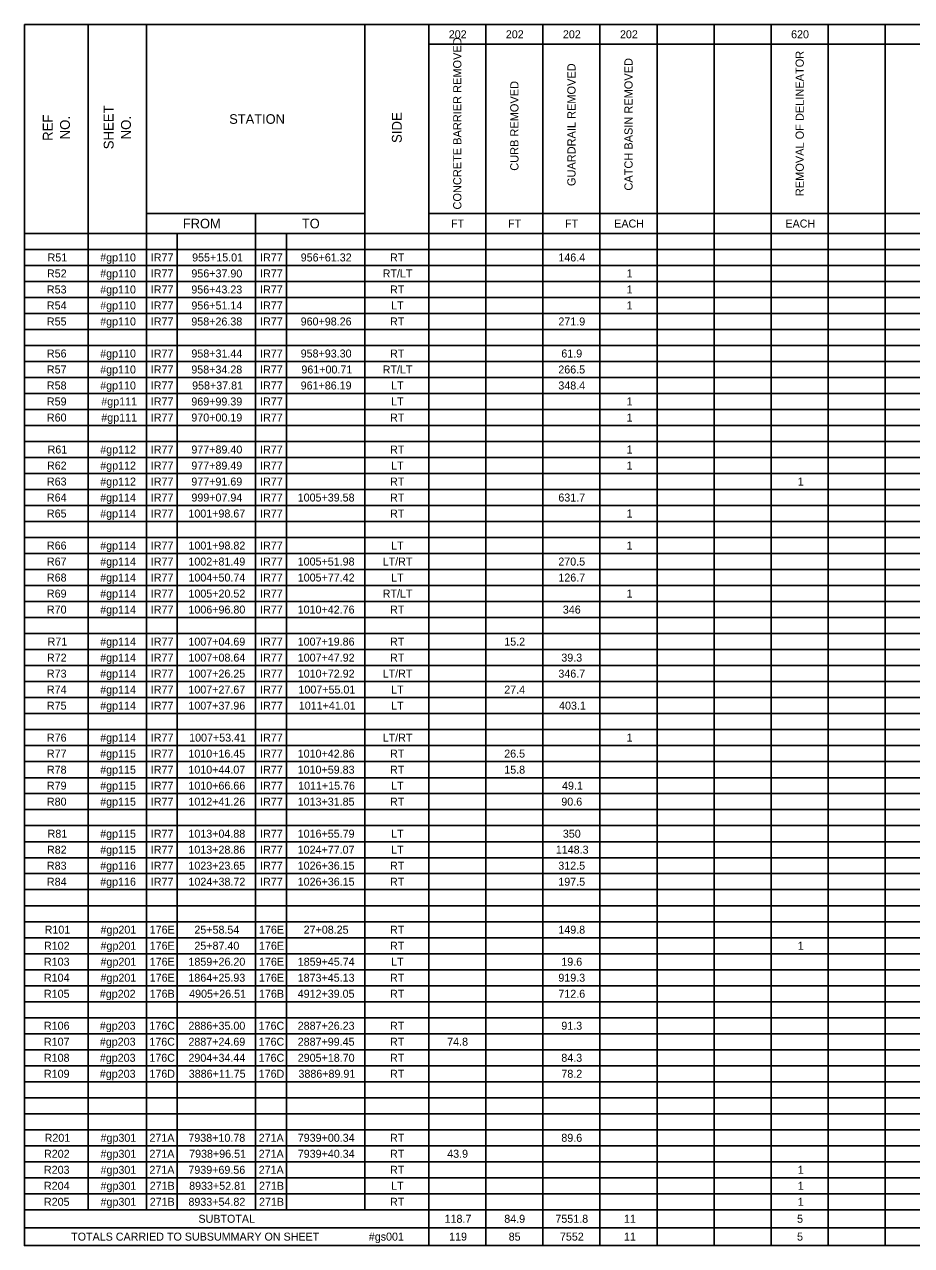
# Model space of a CAD drawing. Extents: x -542 to 295, y -281 to 32.
# Drawn here: x -16.36 to -1.11, y -40.59 to -19.59 of the extents above; entities that cross this region are included whole.
import ezdxf

# ---------------------------------------------------------------- set-up
doc = ezdxf.new("R2010")
doc.units = 0
doc.layers.add('SC_Scratch1', color=7, linetype='Continuous')
doc.layers.add('SH_Text', color=7, linetype='Continuous')

msp = doc.modelspace()

# ---------------------------------------------------------------- linework, layer by layer
at = {"layer": 'SC_Scratch1'}
msp.add_lwpolyline([(-16.359, -19.593), (14.141, -19.593), (14.141, -40.593), (-16.359, -40.593)], close=True, dxfattribs=at)
at = {"layer": 'SH_Text'}
for p, q in [((-16.359, -19.593), (14.136, -19.593)), ((-16.359, -19.593), (-16.359, -40.594)), ((-15.261, -19.593), (-15.261, -39.979)), ((-14.263, -19.593), (-14.263, -39.979)), ((-10.506, -19.593), (-10.506, -39.979)), ((-9.408, -19.593), (-9.408, -40.594)), ((-8.427, -19.593), (-8.427, -40.594)), ((-7.446, -19.593), (-7.446, -40.594)), ((-6.465, -19.593), (-6.465, -40.594)), ((-5.484, -19.593), (-5.484, -40.594)), ((-4.503, -19.593), (-4.503, -40.594)), ((-3.522, -19.593), (-3.522, -40.594)), ((-2.541, -19.593), (-2.541, -40.594)), ((-1.56, -19.593), (-1.56, -40.594)), ((-9.408, -19.933), (14.136, -19.933)), ((-14.263, -22.847), (-10.506, -22.847)), ((-12.385, -22.847), (-12.385, -39.979)), ((-9.408, -22.847), (14.136, -22.847)), ((-16.359, -23.187), (14.136, -23.187)), ((-13.731, -23.187), (-13.731, -39.979)), ((-11.852, -23.187), (-11.852, -39.979)), ((-16.359, -23.463), (14.136, -23.463)), ((-16.359, -23.738), (14.136, -23.738)), ((-16.359, -24.013), (14.136, -24.013)), ((-16.359, -24.288), (14.136, -24.288)), ((-16.359, -24.564), (14.136, -24.564)), ((-16.359, -24.839), (14.136, -24.839)), ((-16.359, -25.114), (14.136, -25.114)), ((-16.359, -25.389), (14.136, -25.389)), ((-16.359, -25.665), (14.136, -25.665)), ((-16.359, -25.94), (14.136, -25.94)), ((-16.359, -26.215), (14.136, -26.215)), ((-16.359, -26.491), (14.136, -26.491)), ((-16.359, -26.766), (14.136, -26.766)), ((-16.359, -27.041), (14.136, -27.041)), ((-16.359, -27.316), (14.136, -27.316)), ((-16.359, -27.592), (14.136, -27.592)), ((-16.359, -27.867), (14.136, -27.867)), ((-16.359, -28.142), (14.136, -28.142)), ((-16.359, -28.417), (14.136, -28.417)), ((-16.359, -28.693), (14.136, -28.693)), ((-16.359, -28.968), (14.136, -28.968)), ((-16.359, -29.243), (14.136, -29.243)), ((-16.359, -29.519), (14.136, -29.519)), ((-16.359, -29.794), (14.136, -29.794)), ((-16.359, -30.069), (14.136, -30.069)), ((-16.359, -30.344), (14.136, -30.344)), ((-16.359, -30.62), (14.136, -30.62)), ((-16.359, -30.895), (14.136, -30.895)), ((-16.359, -31.17), (14.136, -31.17)), ((-16.359, -31.445), (14.136, -31.445)), ((-16.359, -31.721), (14.136, -31.721)), ((-16.359, -31.996), (14.136, -31.996)), ((-16.359, -32.271), (14.136, -32.271)), ((-16.359, -32.547), (14.136, -32.547)), ((-16.359, -32.822), (14.136, -32.822)), ((-16.359, -33.097), (14.136, -33.097)), ((-16.359, -33.372), (14.136, -33.372)), ((-16.359, -33.648), (14.136, -33.648)), ((-16.359, -33.923), (14.136, -33.923)), ((-16.359, -34.198), (14.136, -34.198)), ((-16.359, -34.473), (14.136, -34.473)), ((-16.359, -34.749), (14.136, -34.749)), ((-16.359, -35.024), (14.136, -35.024)), ((-16.359, -35.299), (14.136, -35.299)), ((-16.359, -35.575), (14.136, -35.575)), ((-16.359, -35.85), (14.136, -35.85)), ((-16.359, -36.125), (14.136, -36.125)), ((-16.359, -36.4), (14.136, -36.4)), ((-16.359, -36.676), (14.136, -36.676)), ((-16.359, -36.951), (14.136, -36.951)), ((-16.359, -37.226), (14.136, -37.226)), ((-16.359, -37.501), (14.136, -37.501)), ((-16.359, -37.777), (14.136, -37.777)), ((-16.359, -38.052), (14.136, -38.052)), ((-16.359, -38.327), (14.136, -38.327)), ((-16.359, -38.603), (14.136, -38.603)), ((-16.359, -38.878), (14.136, -38.878)), ((-16.359, -39.153), (14.136, -39.153)), ((-16.359, -39.428), (14.136, -39.428)), ((-16.359, -39.704), (14.136, -39.704)), ((-16.359, -39.979), (14.136, -39.979)), ((-16.359, -40.287), (14.136, -40.287)), ((-16.359, -40.594), (14.136, -40.594))]:
    msp.add_line(p, q, dxfattribs=at)

# ---------------------------------------------------------------- texts
for s, height, p in [('202', 0.1376, (-9.064, -19.831)), ('202', 0.1376, (-8.083, -19.831)), ('202', 0.1376, (-7.102, -19.831)), ('202', 0.1376, (-6.121, -19.831)), ('620', 0.1376, (-3.179, -19.831)), ('STATION', 0.1652, (-12.838, -21.302)), ('FROM', 0.1652, (-13.635, -23.1)), ('TO', 0.1652, (-11.589, -23.1)), ('FT', 0.1376, (-9.026, -23.086)), ('FT', 0.1376, (-8.045, -23.086)), ('FT', 0.1376, (-7.064, -23.086)), ('EACH', 0.1376, (-6.219, -23.086)), ('EACH', 0.1376, (-3.276, -23.086)), ('R51', 0.1376, (-15.96, -23.669)), ('#gp110', 0.1376, (-15.056, -23.669)), ('IR77', 0.1376, (-14.186, -23.669)), ('955+15.01', 0.1376, (-13.476, -23.669)), ('IR77', 0.1376, (-12.307, -23.669)), ('956+61.32', 0.1376, (-11.609, -23.669)), ('RT', 0.1376, (-10.074, -23.669)), ('146.4', 0.1376, (-7.18, -23.669)), ('R52', 0.1376, (-15.971, -23.944)), ('#gp110', 0.1376, (-15.056, -23.944)), ('IR77', 0.1376, (-14.186, -23.944)), ('956+37.90', 0.1376, (-13.488, -23.944)), ('IR77', 0.1376, (-12.307, -23.944)), ('RT/LT', 0.1376, (-10.2, -23.944)), ('1', 0.138, (-6.008, -23.944)), ('R53', 0.1376, (-15.972, -24.22)), ('#gp110', 0.1376, (-15.056, -24.22)), ('IR77', 0.1376, (-14.186, -24.22)), ('956+43.23', 0.1376, (-13.489, -24.22)), ('IR77', 0.1376, (-12.307, -24.22)), ('RT', 0.1376, (-10.074, -24.22)), ('1', 0.138, (-6.008, -24.22)), ('R54', 0.1376, (-15.972, -24.495)), ('#gp110', 0.1376, (-15.056, -24.495)), ('IR77', 0.1376, (-14.186, -24.495)), ('956+51.14', 0.1376, (-13.488, -24.495)), ('IR77', 0.1376, (-12.307, -24.495)), ('LT', 0.1376, (-10.054, -24.495)), ('1', 0.138, (-6.008, -24.495)), ('R55', 0.1376, (-15.972, -24.77)), ('#gp110', 0.1376, (-15.056, -24.77)), ('IR77', 0.1376, (-14.186, -24.77)), ('958+26.38', 0.1376, (-13.489, -24.77)), ('IR77', 0.1376, (-12.307, -24.77)), ('960+98.26', 0.1376, (-11.61, -24.77)), ('RT', 0.1376, (-10.074, -24.77)), ('271.9', 0.1376, (-7.18, -24.77)), ('R56', 0.1376, (-15.972, -25.321)), ('#gp110', 0.1376, (-15.056, -25.321)), ('IR77', 0.1376, (-14.186, -25.321)), ('958+31.44', 0.1376, (-13.488, -25.321)), ('IR77', 0.1376, (-12.307, -25.321)), ('958+93.30', 0.1376, (-11.61, -25.321)), ('RT', 0.1376, (-10.074, -25.321)), ('61.9', 0.1376, (-7.129, -25.321)), ('R57', 0.1376, (-15.972, -25.596)), ('#gp110', 0.1376, (-15.056, -25.596)), ('IR77', 0.1376, (-14.186, -25.596)), ('958+34.28', 0.1376, (-13.489, -25.596)), ('IR77', 0.1376, (-12.307, -25.596)), ('961+00.71', 0.1376, (-11.597, -25.596)), ('RT/LT', 0.1376, (-10.2, -25.596)), ('266.5', 0.1376, (-7.181, -25.596)), ('R58', 0.1376, (-15.972, -25.871)), ('#gp110', 0.1376, (-15.056, -25.871)), ('IR77', 0.1376, (-14.186, -25.871)), ('958+37.81', 0.1376, (-13.476, -25.871)), ('IR77', 0.1376, (-12.307, -25.871)), ('961+86.19', 0.1376, (-11.61, -25.871)), ('LT', 0.1376, (-10.054, -25.871)), ('348.4', 0.1376, (-7.18, -25.871)), ('R59', 0.1376, (-15.972, -26.146)), ('#gp111', 0.1376, (-15.037, -26.146)), ('IR77', 0.1376, (-14.186, -26.146)), ('969+99.39', 0.1376, (-13.489, -26.146)), ('IR77', 0.1376, (-12.307, -26.146)), ('LT', 0.1376, (-10.054, -26.146)), ('1', 0.138, (-6.008, -26.146)), ('R60', 0.1376, (-15.972, -26.422)), ('#gp111', 0.1376, (-15.037, -26.422)), ('IR77', 0.1376, (-14.186, -26.422)), ('970+00.19', 0.1376, (-13.489, -26.422)), ('IR77', 0.1376, (-12.307, -26.422)), ('RT', 0.1376, (-10.074, -26.422)), ('1', 0.138, (-6.008, -26.422)), ('R61', 0.1376, (-15.96, -26.972)), ('#gp112', 0.1376, (-15.055, -26.972)), ('IR77', 0.1376, (-14.186, -26.972)), ('977+89.40', 0.1376, (-13.488, -26.972)), ('IR77', 0.1376, (-12.307, -26.972)), ('RT', 0.1376, (-10.074, -26.972)), ('1', 0.138, (-6.008, -26.972)), ('R62', 0.1376, (-15.971, -27.248)), ('#gp112', 0.1376, (-15.055, -27.248)), ('IR77', 0.1376, (-14.186, -27.248)), ('977+89.49', 0.1376, (-13.489, -27.248)), ('IR77', 0.1376, (-12.307, -27.248)), ('LT', 0.1376, (-10.054, -27.248)), ('1', 0.138, (-6.008, -27.248)), ('R63', 0.1376, (-15.972, -27.523)), ('#gp112', 0.1376, (-15.055, -27.523)), ('IR77', 0.1376, (-14.186, -27.523)), ('977+91.69', 0.1376, (-13.489, -27.523)), ('IR77', 0.1376, (-12.307, -27.523)), ('RT', 0.1376, (-10.074, -27.523)), ('1', 0.138, (-3.065, -27.523)), ('R64', 0.1376, (-15.972, -27.798)), ('#gp114', 0.1376, (-15.056, -27.798)), ('IR77', 0.1376, (-14.186, -27.798)), ('999+07.94', 0.1376, (-13.488, -27.798)), ('IR77', 0.1376, (-12.307, -27.798)), ('1005+39.58', 0.1376, (-11.661, -27.798)), ('RT', 0.1376, (-10.074, -27.798)), ('631.7', 0.1376, (-7.18, -27.798)), ('R65', 0.1376, (-15.972, -28.073)), ('#gp114', 0.1376, (-15.056, -28.073)), ('IR77', 0.1376, (-14.186, -28.073)), ('1001+98.67', 0.1376, (-13.54, -28.073)), ('IR77', 0.1376, (-12.307, -28.073)), ('RT', 0.1376, (-10.074, -28.073)), ('1', 0.138, (-6.008, -28.073)), ('R66', 0.1376, (-15.972, -28.624)), ('#gp114', 0.1376, (-15.056, -28.624)), ('IR77', 0.1376, (-14.186, -28.624)), ('1001+98.82', 0.1376, (-13.539, -28.624)), ('IR77', 0.1376, (-12.307, -28.624)), ('LT', 0.1376, (-10.054, -28.624)), ('1', 0.138, (-6.008, -28.624)), ('R67', 0.1376, (-15.972, -28.899)), ('#gp114', 0.1376, (-15.056, -28.899)), ('IR77', 0.1376, (-14.186, -28.899)), ('1002+81.49', 0.1376, (-13.54, -28.899)), ('IR77', 0.1376, (-12.307, -28.899)), ('1005+51.98', 0.1376, (-11.661, -28.899)), ('LT/RT', 0.1376, (-10.2, -28.899)), ('270.5', 0.1376, (-7.181, -28.899)), ('R68', 0.1376, (-15.972, -29.174)), ('#gp114', 0.1376, (-15.056, -29.174)), ('IR77', 0.1376, (-14.186, -29.174)), ('1004+50.74', 0.1376, (-13.539, -29.174)), ('IR77', 0.1376, (-12.307, -29.174)), ('1005+77.42', 0.1376, (-11.66, -29.174)), ('LT', 0.1376, (-10.054, -29.174)), ('126.7', 0.1376, (-7.18, -29.174)), ('R69', 0.1376, (-15.972, -29.45)), ('#gp114', 0.1376, (-15.056, -29.45)), ('IR77', 0.1376, (-14.186, -29.45)), ('1005+20.52', 0.1376, (-13.539, -29.45)), ('IR77', 0.1376, (-12.307, -29.45)), ('RT/LT', 0.1376, (-10.2, -29.45)), ('1', 0.138, (-6.008, -29.45)), ('R70', 0.1376, (-15.972, -29.725)), ('#gp114', 0.1376, (-15.056, -29.725)), ('IR77', 0.1376, (-14.186, -29.725)), ('1006+96.80', 0.1376, (-13.539, -29.725)), ('IR77', 0.1376, (-12.307, -29.725)), ('1010+42.76', 0.1376, (-11.661, -29.725)), ('RT', 0.1376, (-10.074, -29.725)), ('346', 0.1376, (-7.103, -29.725)), ('R71', 0.1376, (-15.96, -30.276)), ('#gp114', 0.1376, (-15.056, -30.276)), ('IR77', 0.1376, (-14.186, -30.276)), ('1007+04.69', 0.1376, (-13.54, -30.276)), ('IR77', 0.1376, (-12.307, -30.276)), ('1007+19.86', 0.1376, (-11.661, -30.276)), ('RT', 0.1376, (-10.074, -30.276)), ('15.2', 0.1376, (-8.11, -30.276)), ('R72', 0.1376, (-15.971, -30.551)), ('#gp114', 0.1376, (-15.056, -30.551)), ('IR77', 0.1376, (-14.186, -30.551)), ('1007+08.64', 0.1376, (-13.539, -30.551)), ('IR77', 0.1376, (-12.307, -30.551)), ('1007+47.92', 0.1376, (-11.66, -30.551)), ('RT', 0.1376, (-10.074, -30.551)), ('39.3', 0.1376, (-7.129, -30.551)), ('R73', 0.1376, (-15.972, -30.826)), ('#gp114', 0.1376, (-15.056, -30.826)), ('IR77', 0.1376, (-14.186, -30.826)), ('1007+26.25', 0.1376, (-13.54, -30.826)), ('IR77', 0.1376, (-12.307, -30.826)), ('1010+72.92', 0.1376, (-11.66, -30.826)), ('LT/RT', 0.1376, (-10.2, -30.826)), ('346.7', 0.1376, (-7.18, -30.826)), ('R74', 0.1376, (-15.972, -31.101)), ('#gp114', 0.1376, (-15.056, -31.101)), ('IR77', 0.1376, (-14.186, -31.101)), ('1007+27.67', 0.1376, (-13.54, -31.101)), ('IR77', 0.1376, (-12.307, -31.101)), ('1007+55.01', 0.1376, (-11.648, -31.101)), ('LT', 0.1376, (-10.054, -31.101)), ('27.4', 0.1376, (-8.11, -31.101)), ('R75', 0.1376, (-15.972, -31.377)), ('#gp114', 0.1376, (-15.056, -31.377)), ('IR77', 0.1376, (-14.186, -31.377)), ('1007+37.96', 0.1376, (-13.54, -31.377)), ('IR77', 0.1376, (-12.307, -31.377)), ('1011+41.01', 0.1376, (-11.642, -31.377)), ('LT', 0.1376, (-10.054, -31.377)), ('403.1', 0.1376, (-7.168, -31.377)), ('R76', 0.1376, (-15.972, -31.927)), ('#gp114', 0.1376, (-15.056, -31.927)), ('IR77', 0.1376, (-14.186, -31.927)), ('1007+53.41', 0.1376, (-13.527, -31.927)), ('IR77', 0.1376, (-12.307, -31.927)), ('LT/RT', 0.1376, (-10.2, -31.927)), ('1', 0.138, (-6.008, -31.927)), ('R77', 0.1376, (-15.972, -32.202)), ('#gp115', 0.1376, (-15.056, -32.202)), ('IR77', 0.1376, (-14.186, -32.202)), ('1010+16.45', 0.1376, (-13.54, -32.202)), ('IR77', 0.1376, (-12.307, -32.202)), ('1010+42.86', 0.1376, (-11.661, -32.202)), ('RT', 0.1376, (-10.074, -32.202)), ('26.5', 0.1376, (-8.111, -32.202)), ('R78', 0.1376, (-15.972, -32.478)), ('#gp115', 0.1376, (-15.056, -32.478)), ('IR77', 0.1376, (-14.186, -32.478)), ('1010+44.07', 0.1376, (-13.54, -32.478)), ('IR77', 0.1376, (-12.307, -32.478)), ('1010+59.83', 0.1376, (-11.661, -32.478)), ('RT', 0.1376, (-10.074, -32.478)), ('15.8', 0.1376, (-8.11, -32.478)), ('R79', 0.1376, (-15.972, -32.753)), ('#gp115', 0.1376, (-15.056, -32.753)), ('IR77', 0.1376, (-14.186, -32.753)), ('1010+66.66', 0.1376, (-13.54, -32.753)), ('IR77', 0.1376, (-12.307, -32.753)), ('1011+15.76', 0.1376, (-11.654, -32.753)), ('LT', 0.1376, (-10.054, -32.753)), ('49.1', 0.1376, (-7.117, -32.753)), ('R80', 0.1376, (-15.972, -33.028)), ('#gp115', 0.1376, (-15.056, -33.028)), ('IR77', 0.1376, (-14.186, -33.028)), ('1012+41.26', 0.1376, (-13.54, -33.028)), ('IR77', 0.1376, (-12.307, -33.028)), ('1013+31.85', 0.1376, (-11.661, -33.028)), ('RT', 0.1376, (-10.074, -33.028)), ('90.6', 0.1376, (-7.129, -33.028)), ('R81', 0.1376, (-15.96, -33.579)), ('#gp115', 0.1376, (-15.056, -33.579)), ('IR77', 0.1376, (-14.186, -33.579)), ('1013+04.88', 0.1376, (-13.54, -33.579)), ('IR77', 0.1376, (-12.307, -33.579)), ('1016+55.79', 0.1376, (-11.661, -33.579)), ('LT', 0.1376, (-10.054, -33.579)), ('350', 0.1376, (-7.103, -33.579)), ('R82', 0.1376, (-15.971, -33.854)), ('#gp115', 0.1376, (-15.056, -33.854)), ('IR77', 0.1376, (-14.186, -33.854)), ('1013+28.86', 0.1376, (-13.54, -33.854)), ('IR77', 0.1376, (-12.307, -33.854)), ('1024+77.07', 0.1376, (-11.661, -33.854)), ('LT', 0.1376, (-10.054, -33.854)), ('1148.3', 0.1376, (-7.224, -33.854)), ('R83', 0.1376, (-15.972, -34.129)), ('#gp116', 0.1376, (-15.056, -34.129)), ('IR77', 0.1376, (-14.186, -34.129)), ('1023+23.65', 0.1376, (-13.54, -34.129)), ('IR77', 0.1376, (-12.307, -34.129)), ('1026+36.15', 0.1376, (-11.661, -34.129)), ('RT', 0.1376, (-10.074, -34.129)), ('312.5', 0.1376, (-7.181, -34.129)), ('R84', 0.1376, (-15.972, -34.405)), ('#gp116', 0.1376, (-15.056, -34.405)), ('IR77', 0.1376, (-14.186, -34.405)), ('1024+38.72', 0.1376, (-13.539, -34.405)), ('IR77', 0.1376, (-12.307, -34.405)), ('1026+36.15', 0.1376, (-11.661, -34.405)), ('RT', 0.1376, (-10.074, -34.405)), ('197.5', 0.1376, (-7.181, -34.405)), ('R101', 0.1376, (-16.011, -35.23)), ('#gp201', 0.1376, (-15.05, -35.23)), ('176E', 0.1376, (-14.205, -35.23)), ('25+58.54', 0.1376, (-13.437, -35.23)), ('176E', 0.1376, (-12.326, -35.23)), ('27+08.25', 0.1376, (-11.559, -35.23)), ('RT', 0.1376, (-10.074, -35.23)), ('149.8', 0.1376, (-7.18, -35.23)), ('R102', 0.1376, (-16.022, -35.506)), ('#gp201', 0.1376, (-15.05, -35.506)), ('176E', 0.1376, (-14.205, -35.506)), ('25+87.40', 0.1376, (-13.437, -35.506)), ('176E', 0.1376, (-12.326, -35.506)), ('RT', 0.1376, (-10.074, -35.506)), ('1', 0.138, (-3.065, -35.506)), ('R103', 0.1376, (-16.023, -35.781)), ('#gp201', 0.1376, (-15.05, -35.781)), ('176E', 0.1376, (-14.205, -35.781)), ('1859+26.20', 0.1376, (-13.539, -35.781)), ('176E', 0.1376, (-12.326, -35.781)), ('1859+45.74', 0.1376, (-11.66, -35.781)), ('LT', 0.1376, (-10.054, -35.781)), ('19.6', 0.1376, (-7.129, -35.781)), ('R104', 0.1376, (-16.023, -36.056)), ('#gp201', 0.1376, (-15.05, -36.056)), ('176E', 0.1376, (-14.205, -36.056)), ('1864+25.93', 0.1376, (-13.54, -36.056)), ('176E', 0.1376, (-12.326, -36.056)), ('1873+45.13', 0.1376, (-11.661, -36.056)), ('RT', 0.1376, (-10.074, -36.056)), ('919.3', 0.1376, (-7.18, -36.056)), ('R105', 0.1376, (-16.023, -36.332)), ('#gp202', 0.1376, (-15.062, -36.332)), ('176B', 0.1376, (-14.205, -36.332)), ('4905+26.51', 0.1376, (-13.527, -36.332)), ('176B', 0.1376, (-12.326, -36.332)), ('4912+39.05', 0.1376, (-11.661, -36.332)), ('RT', 0.1376, (-10.074, -36.332)), ('712.6', 0.1376, (-7.18, -36.332)), ('R106', 0.1376, (-16.023, -36.882)), ('#gp203', 0.1376, (-15.062, -36.882)), ('176C', 0.1376, (-14.211, -36.882)), ('2886+35.00', 0.1376, (-13.539, -36.882)), ('176C', 0.1376, (-12.332, -36.882)), ('2887+26.23', 0.1376, (-11.661, -36.882)), ('RT', 0.1376, (-10.074, -36.882)), ('91.3', 0.1376, (-7.129, -36.882)), ('R107', 0.1376, (-16.023, -37.157)), ('#gp203', 0.1376, (-15.062, -37.157)), ('176C', 0.1376, (-14.211, -37.157)), ('2887+24.69', 0.1376, (-13.54, -37.157)), ('176C', 0.1376, (-12.332, -37.157)), ('2887+99.45', 0.1376, (-11.661, -37.157)), ('RT', 0.1376, (-10.074, -37.157)), ('74.8', 0.1376, (-9.091, -37.157)), ('R108', 0.1376, (-16.023, -37.433)), ('#gp203', 0.1376, (-15.062, -37.433)), ('176C', 0.1376, (-14.211, -37.433)), ('2904+34.44', 0.1376, (-13.539, -37.433)), ('176C', 0.1376, (-12.332, -37.433)), ('2905+18.70', 0.1376, (-11.66, -37.433)), ('RT', 0.1376, (-10.074, -37.433)), ('84.3', 0.1376, (-7.129, -37.433)), ('R109', 0.1376, (-16.023, -37.708)), ('#gp203', 0.1376, (-15.062, -37.708)), ('176D', 0.1376, (-14.21, -37.708)), ('3886+11.75', 0.1376, (-13.534, -37.708)), ('176D', 0.1376, (-12.331, -37.708)), ('3886+89.91', 0.1376, (-11.648, -37.708)), ('RT', 0.1376, (-10.074, -37.708)), ('78.2', 0.1376, (-7.128, -37.708)), ('R201', 0.1376, (-16.011, -38.809)), ('#gp301', 0.1376, (-15.05, -38.809)), ('271A', 0.1376, (-14.21, -38.809)), ('7938+10.78', 0.1376, (-13.54, -38.809)), ('271A', 0.1376, (-12.331, -38.809)), ('7939+00.34', 0.1376, (-11.66, -38.809)), ('RT', 0.1376, (-10.074, -38.809)), ('89.6', 0.1376, (-7.129, -38.809)), ('R202', 0.1376, (-16.022, -39.084)), ('#gp301', 0.1376, (-15.05, -39.084)), ('271A', 0.1376, (-14.21, -39.084)), ('7938+96.51', 0.1376, (-13.527, -39.084)), ('271A', 0.1376, (-12.331, -39.084)), ('7939+40.34', 0.1376, (-11.66, -39.084)), ('RT', 0.1376, (-10.074, -39.084)), ('43.9', 0.1376, (-9.091, -39.084)), ('R203', 0.1376, (-16.023, -39.36)), ('#gp301', 0.1376, (-15.05, -39.36)), ('271A', 0.1376, (-14.21, -39.36)), ('7939+69.56', 0.1376, (-13.54, -39.36)), ('271A', 0.1376, (-12.331, -39.36)), ('RT', 0.1376, (-10.074, -39.36)), ('1', 0.138, (-3.065, -39.36)), ('R204', 0.1376, (-16.023, -39.635)), ('#gp301', 0.1376, (-15.05, -39.635)), ('271B', 0.1376, (-14.205, -39.635)), ('8933+52.81', 0.1376, (-13.527, -39.635)), ('271B', 0.1376, (-12.326, -39.635)), ('LT', 0.1376, (-10.054, -39.635)), ('1', 0.138, (-3.065, -39.635)), ('R205', 0.1376, (-16.023, -39.91)), ('#gp301', 0.1376, (-15.05, -39.91)), ('271B', 0.1376, (-14.205, -39.91)), ('8933+54.82', 0.1376, (-13.539, -39.91)), ('271B', 0.1376, (-12.326, -39.91)), ('RT', 0.1376, (-10.074, -39.91)), ('1', 0.138, (-3.065, -39.91)), ('SUBTOTAL', 0.1376, (-13.367, -40.202)), ('118.7', 0.1376, (-9.136, -40.202)), ('84.9', 0.1376, (-8.11, -40.202)), ('7551.8', 0.1376, (-7.231, -40.202)), ('11', 0.1376, (-6.052, -40.202)), ('5', 0.138, (-3.077, -40.202)), ('TOTALS CARRIED TO SUBSUMMARY ON SHEET', 0.13764, (-15.555, -40.509)), ('#gs001', 0.1376, (-10.439, -40.509)), ('119', 0.1376, (-9.058, -40.509)), ('85', 0.1376, (-8.034, -40.509)), ('7552', 0.1376, (-7.153, -40.509)), ('11', 0.1376, (-6.052, -40.509)), ('5', 0.138, (-3.077, -40.509))]:
    msp.add_text(s, height=height, dxfattribs=at).set_placement(p)
for s, height, p in [('CONCRETE BARRIER REMOVED', 0.14133, (-8.847, -22.776)), ('REMOVAL OF DELINEATOR', 0.14133, (-2.961, -22.546)), ('GUARDRAIL REMOVED', 0.14133, (-6.885, -22.373)), ('CATCH BASIN REMOVED', 0.14133, (-5.904, -22.45)), ('CURB REMOVED', 0.14133, (-7.866, -22.109)), ('SHEET', 0.1696, (-14.826, -21.74)), ('REF', 0.1696, (-15.873, -21.596)), ('NO.', 0.1696, (-15.577, -21.57)), ('NO.', 0.1696, (-14.529, -21.57)), ('SIDE', 0.1696, (-9.872, -21.632))]:
    msp.add_text(s, height=height, rotation=90, dxfattribs=at).set_placement(p)

doc.saveas('drawing.dxf')
